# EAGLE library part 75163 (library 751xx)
75xxx DEVICE
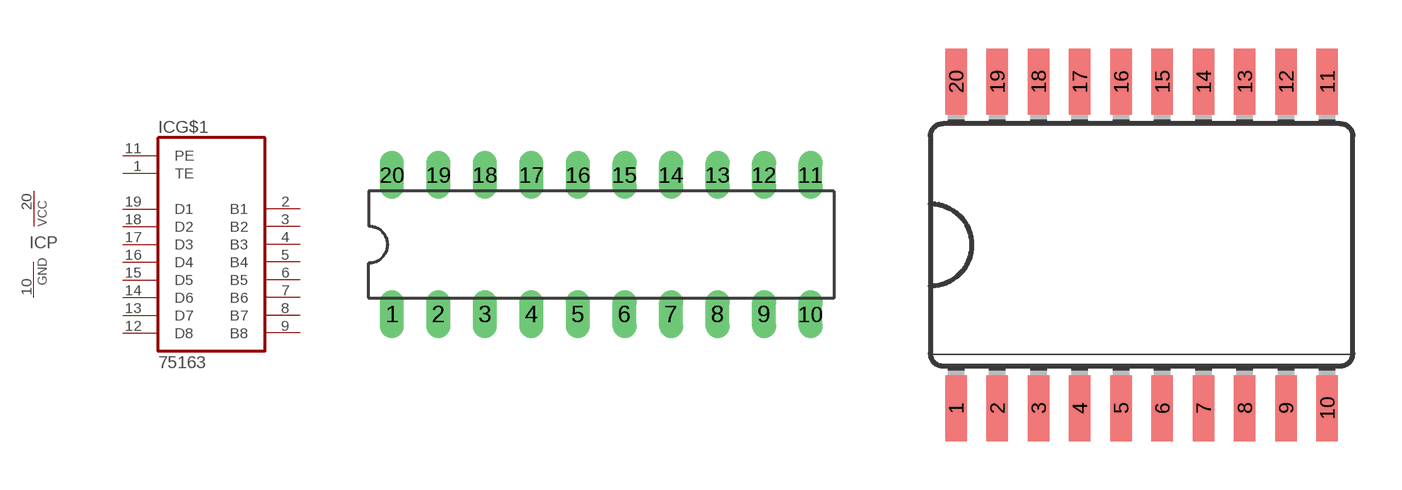
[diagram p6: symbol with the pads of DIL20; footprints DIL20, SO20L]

Designator prefix IC; gates G$1=75163 P=PWRN

## 75163P  [DIL20]
1  G$1:TE  in
2  G$1:B1
3  G$1:B2
4  G$1:B3
5  G$1:B4
6  G$1:B5
7  G$1:B6
8  G$1:B7
9  G$1:B8
10  P:GND  pwr
11  G$1:PE  in
12  G$1:D8
13  G$1:D7
14  G$1:D6
15  G$1:D5
16  G$1:D4
17  G$1:D3
18  G$1:D2
19  G$1:D1
20  P:VCC  pwr

## 75163SO  [SO20L]
Pads as for DIL20

## Footprint DIL20 (pad centres in mm)
Dual In Line Package
drill 0.813 long: 1 -11.43,-3.81; 2 -8.89,-3.81; 3 -6.35,-3.81; 4 -3.81,-3.81; 5 -1.27,-3.81; 6 1.27,-3.81; 7 3.81,-3.81; 8 6.35,-3.81; 9 8.89,-3.81; 10 11.43,-3.81; 11 11.43,3.81; 12 8.89,3.81; 13 6.35,3.81; 14 3.81,3.81; 15 1.27,3.81; 16 -1.27,3.81; 17 -3.81,3.81; 18 -6.35,3.81; 19 -8.89,3.81; 20 -11.43,3.81

## Footprint SO20L (pad centres in mm)
Small Outline package large
smd 0.66 x 2.032: 1 -5.715,-5.029; 2 -4.445,-5.029; 3 -3.175,-5.029; 4 -1.905,-5.029; 5 -0.635,-5.029; 6 0.635,-5.029; 7 1.905,-5.029; 8 3.175,-5.029; 9 4.445,-5.029; 10 5.715,-5.029; 11 5.715,5.029; 12 4.445,5.029; 13 3.175,5.029; 14 1.905,5.029; 15 0.635,5.029; 16 -0.635,5.029; 17 -1.905,5.029; 18 -3.175,5.029; 19 -4.445,5.029; 20 -5.715,5.029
